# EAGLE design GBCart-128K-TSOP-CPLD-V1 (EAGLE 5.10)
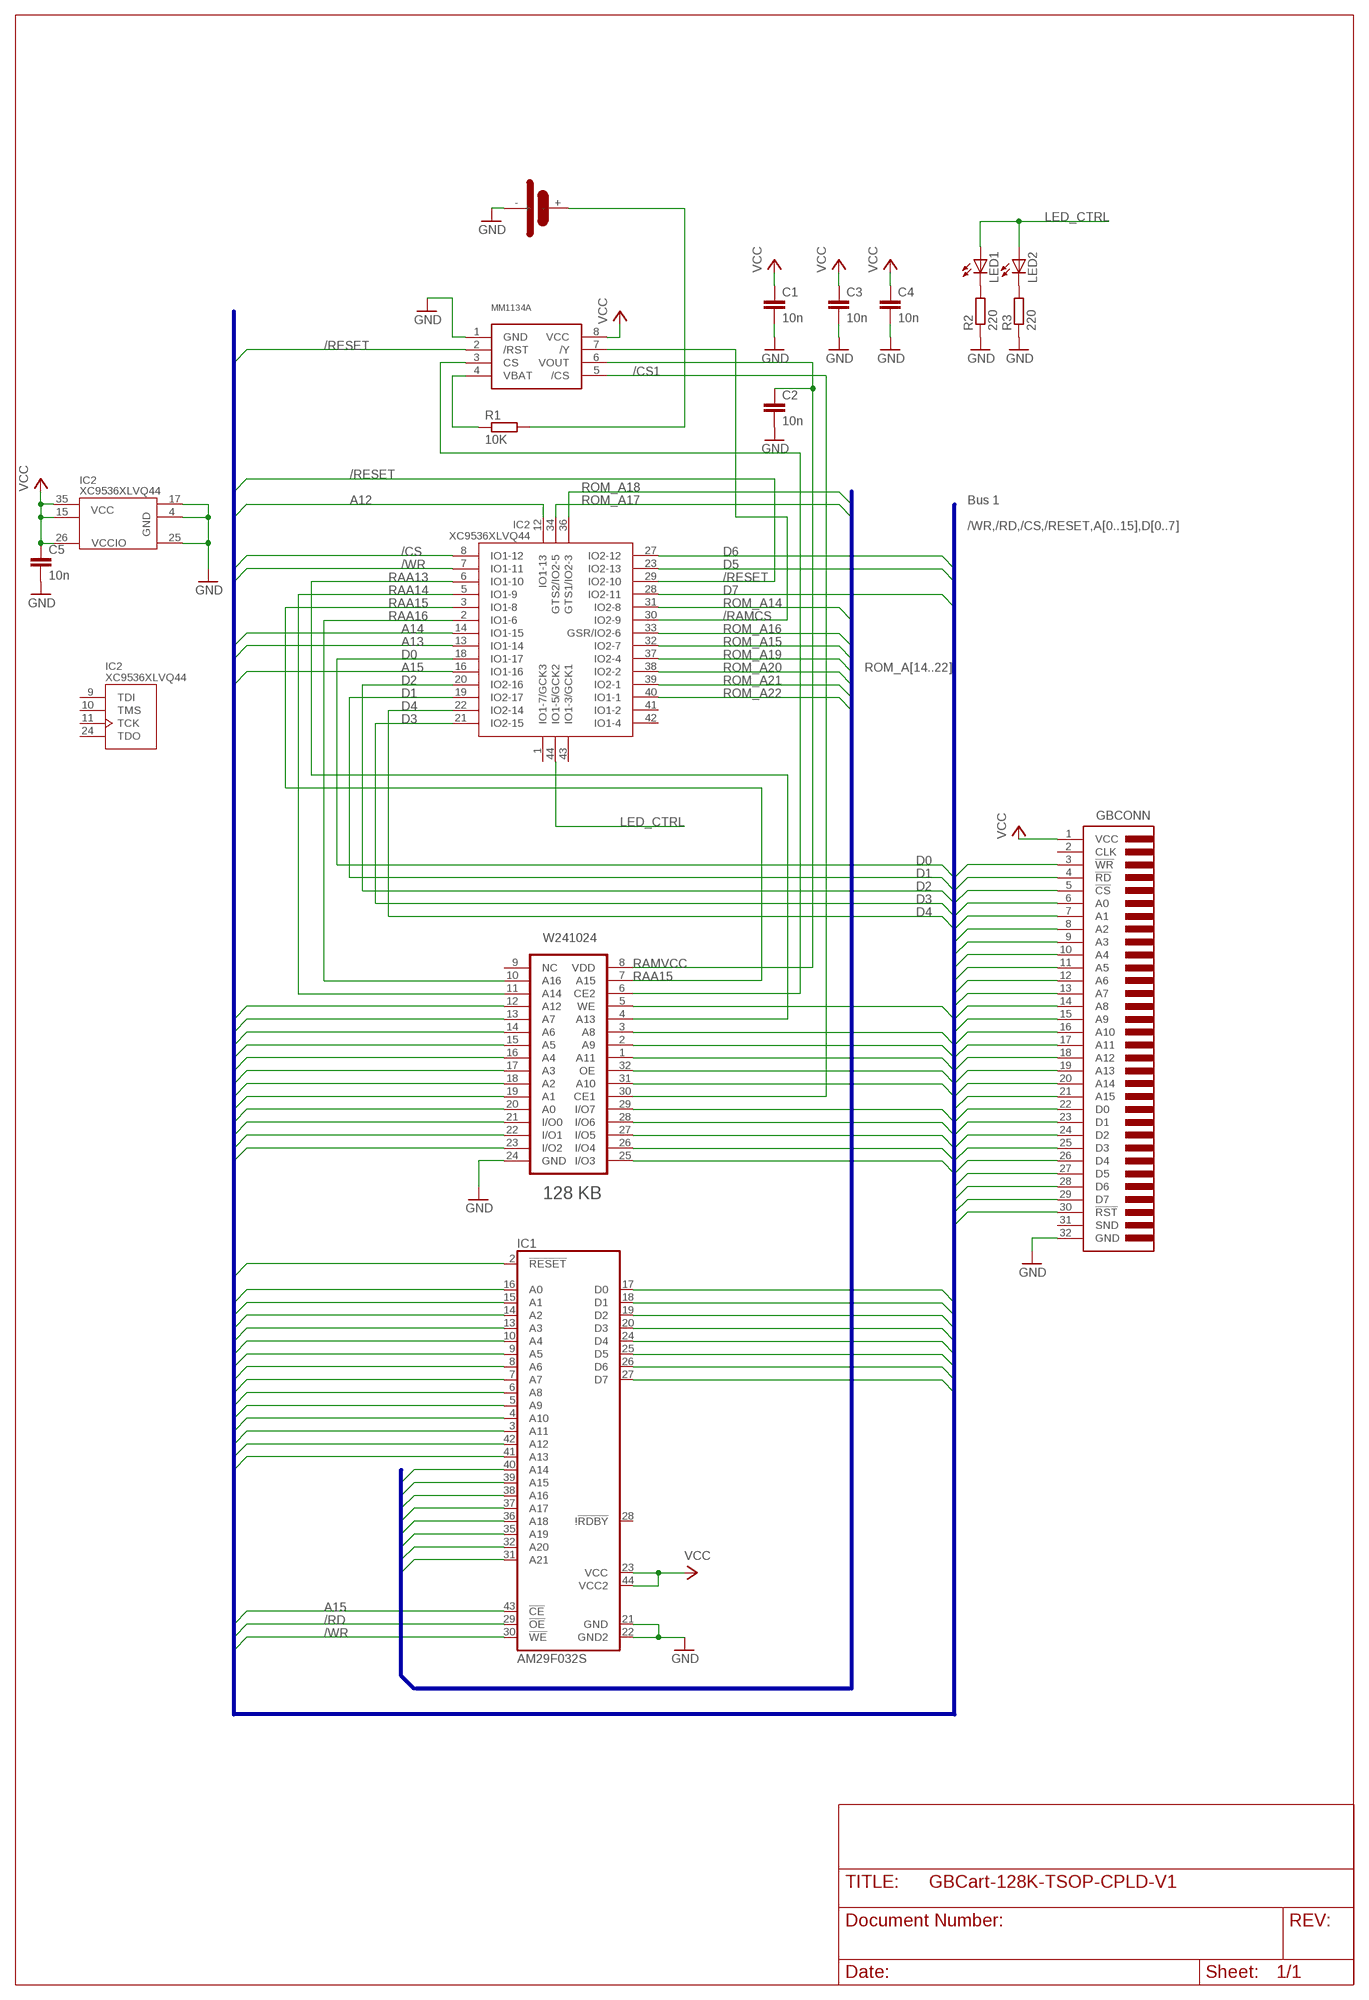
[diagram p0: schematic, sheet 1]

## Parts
C1  10n  C-EUC0805  [C0805]
C2  10n  C-EUC0805  [C0805]
C3  10n  C-EUC0805  [C0805]
C4  10n  C-EUC0805  [C0805]
C5  10n  C-EUC0805  [C0805]
GBCONN  GBCART-FULL  [GBCART]
IC1  AM29F032S  [SO44]
IC2  XC9536XLVQ44  [VQFP44]
IC3  1MBIT SRAM  W241024AT  [TSOP32]
IC4  MM1134A  [SOP08]
LED1  LEDCHIPLED_1206  [CHIPLED_1206]
LED2  LEDCHIPLED_1206  [CHIPLED_1206]
R1  10K  R-EU_R0805  [R0805]
R2  220  R-EU_R0805  [R0805]
R3  220  R-EU_R0805  [R0805]
U$1  CR1616  [CR1616]

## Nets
/CS [Signal]: GBCONN.5(!CS) IC2.8(IO1-12)
/CS1 [Signal]: IC3.30(CE1) IC4.5(/CS)
/CS2: IC3.6(CE2) IC4.3(CS)
/RAMCS [Signal]: IC2.30(IO2-9) IC4.7(/Y)
/RD [Signal]: GBCONN.4(!RD) IC1.29(!OE) IC3.32(OE)
/RESET [Signal]: GBCONN.30(!RST) IC1.2(!RESET) IC2.29(IO2-10) IC4.2(/RST)
/WR [Signal]: GBCONN.3(!WR) IC1.30(!WE) IC2.7(IO1-11) IC3.5(WE)
A0 [Signal]: GBCONN.6(A0) IC1.16(A0) IC3.20(A0)
A1 [Signal]: GBCONN.7(A1) IC1.15(A1) IC3.19(A1)
A2 [Signal]: GBCONN.8(A2) IC1.14(A2) IC3.18(A2)
A3 [Signal]: GBCONN.9(A3) IC1.13(A3) IC3.17(A3)
A4 [Signal]: GBCONN.10(A4) IC1.10(A4) IC3.16(A4)
A5 [Signal]: GBCONN.11(A5) IC1.9(A5) IC3.15(A5)
A6 [Signal]: GBCONN.12(A6) IC1.8(A6) IC3.14(A6)
A7 [Signal]: GBCONN.13(A7) IC1.7(A7) IC3.13(A7)
A8 [Signal]: GBCONN.14(A8) IC1.6(A8) IC3.3(A8)
A9 [Signal]: GBCONN.15(A9) IC1.5(A9) IC3.2(A9)
A10 [Signal]: GBCONN.16(A10) IC1.4(A10) IC3.31(A10)
A11 [Signal]: GBCONN.17(A11) IC1.3(A11) IC3.1(A11)
A12 [Signal]: GBCONN.18(A12) IC1.42(A12) IC2.12(IO1-13) IC3.12(A12)
A13 [Signal]: GBCONN.19(A13) IC1.41(A13) IC2.13(IO1-14)
A14 [Signal]: GBCONN.20(A14) IC2.14(IO1-15)
A15 [Signal]: GBCONN.21(A15) IC1.43(!CE) IC2.16(IO1-16)
D0 [Signal]: GBCONN.22(D0) IC1.17(D0) IC2.18(IO1-17) IC3.21(I/O0)
D1 [Signal]: GBCONN.23(D1) IC1.18(D1) IC2.19(IO2-17) IC3.22(I/O1)
D2 [Signal]: GBCONN.24(D2) IC1.19(D2) IC2.20(IO2-16) IC3.23(I/O2)
D3 [Signal]: GBCONN.25(D3) IC1.20(D3) IC2.21(IO2-15) IC3.25(I/O3)
D4 [Signal]: GBCONN.26(D4) IC1.24(D4) IC2.22(IO2-14) IC3.26(I/O4)
D5 [Signal]: GBCONN.27(D5) IC1.25(D5) IC2.23(IO2-13) IC3.27(I/O5)
D6 [Signal]: GBCONN.28(D6) IC1.26(D6) IC2.27(IO2-12) IC3.28(I/O6)
D7 [Signal]: GBCONN.29(D7) IC1.27(D7) IC2.28(IO2-11) IC3.29(I/O7)
GND: C1.2 C2.2 C3.2 C4.2 C5.2 GBCONN.32(GND) IC1.21(GND) IC1.22(GND2) IC2.4(GND) IC2.17(GND) IC2.25(GND) IC3.24(GND) IC4.1(GND) R2.1 R3.1 U$1.-
LED_CTRL: IC2.44(IO1-5/GCK2) LED1.A LED2.A
N$3: LED1.C R2.2
N$4: IC4.4(VBAT) R1.1
N$5: R1.2 U$1.+
N$6: LED2.C R3.2
RAA13: IC2.6(IO1-10) IC3.4(A13)
RAA14: IC2.5(IO1-9) IC3.11(A14)
RAA15: IC2.3(IO1-8) IC3.7(A15)
RAA16: IC2.2(IO1-6) IC3.10(A16)
RAMVCC: C2.1 IC3.8(VDD) IC4.6(VOUT)
ROM_A14 [Signal]: IC1.40(A14) IC2.31(IO2-8)
ROM_A15 [Signal]: IC1.39(A15) IC2.32(IO2-7)
ROM_A16 [Signal]: IC1.38(A16) IC2.33(GSR/IO2-6)
ROM_A17 [Signal]: IC1.37(A17) IC2.34(GTS2/IO2-5)
ROM_A18 [Signal]: IC1.36(A18) IC2.36(GTS1/IO2-3)
ROM_A19 [Signal]: IC1.35(A19) IC2.37(IO2-4)
ROM_A20 [Signal]: IC1.32(A20) IC2.38(IO2-2)
ROM_A21 [Signal]: IC1.31(A21) IC2.39(IO2-1)
ROM_A22: IC2.40(IO1-1)
VCC: C1.1 C3.1 C4.1 C5.1 GBCONN.1(VCC) IC1.23(VCC) IC1.44(VCC2) IC2.15(VCCINT) IC2.26(VCCIO) IC2.35(VCCINT) IC4.8(VCC)
Unconnected: GBCONN.2(CLK) GBCONN.31(SND) IC1.28(!!RDBY) IC2.1(IO1-7/GCK3) IC2.9(TDI) IC2.10(TMS) IC2.11(TCK) IC2.24(TDO) IC2.41(IO1-2) IC2.42(IO1-4) IC2.43(IO1-3/GCK1) IC3.9(NC)

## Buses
/WR,/RD,/CS,/RESET,A[0..15],D[0..7]
ROM_A[14..22]

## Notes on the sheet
- Bus 1

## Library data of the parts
C1-C5 = rcl:C-EU: CAPACITOR, European symbol
GBCONN = gameboy:GBCART
IC1 = gameboy:AM29F032S: 4-Megabit FLASH MEMORY (512 K x 8 bit/256 K x 16 Bit) 5 V-only
IC2 = enut202:XC9536XL: IC - CPLD, Xlinx 36 macrocells 34 user I/O pins
IC3 = gameboy:W241024AT
IC4 = gameboy:MM1134A
LED1 LED2 = led:LED: LED
R1-R3 = rcl:R-EU_: RESISTOR, European symbol
U$1 = gameboy:CR1616

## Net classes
0 Supply: width 0.254 mm, clearance 0.254 mm
1 Signal: width 0.15 mm, clearance 0.15 mm

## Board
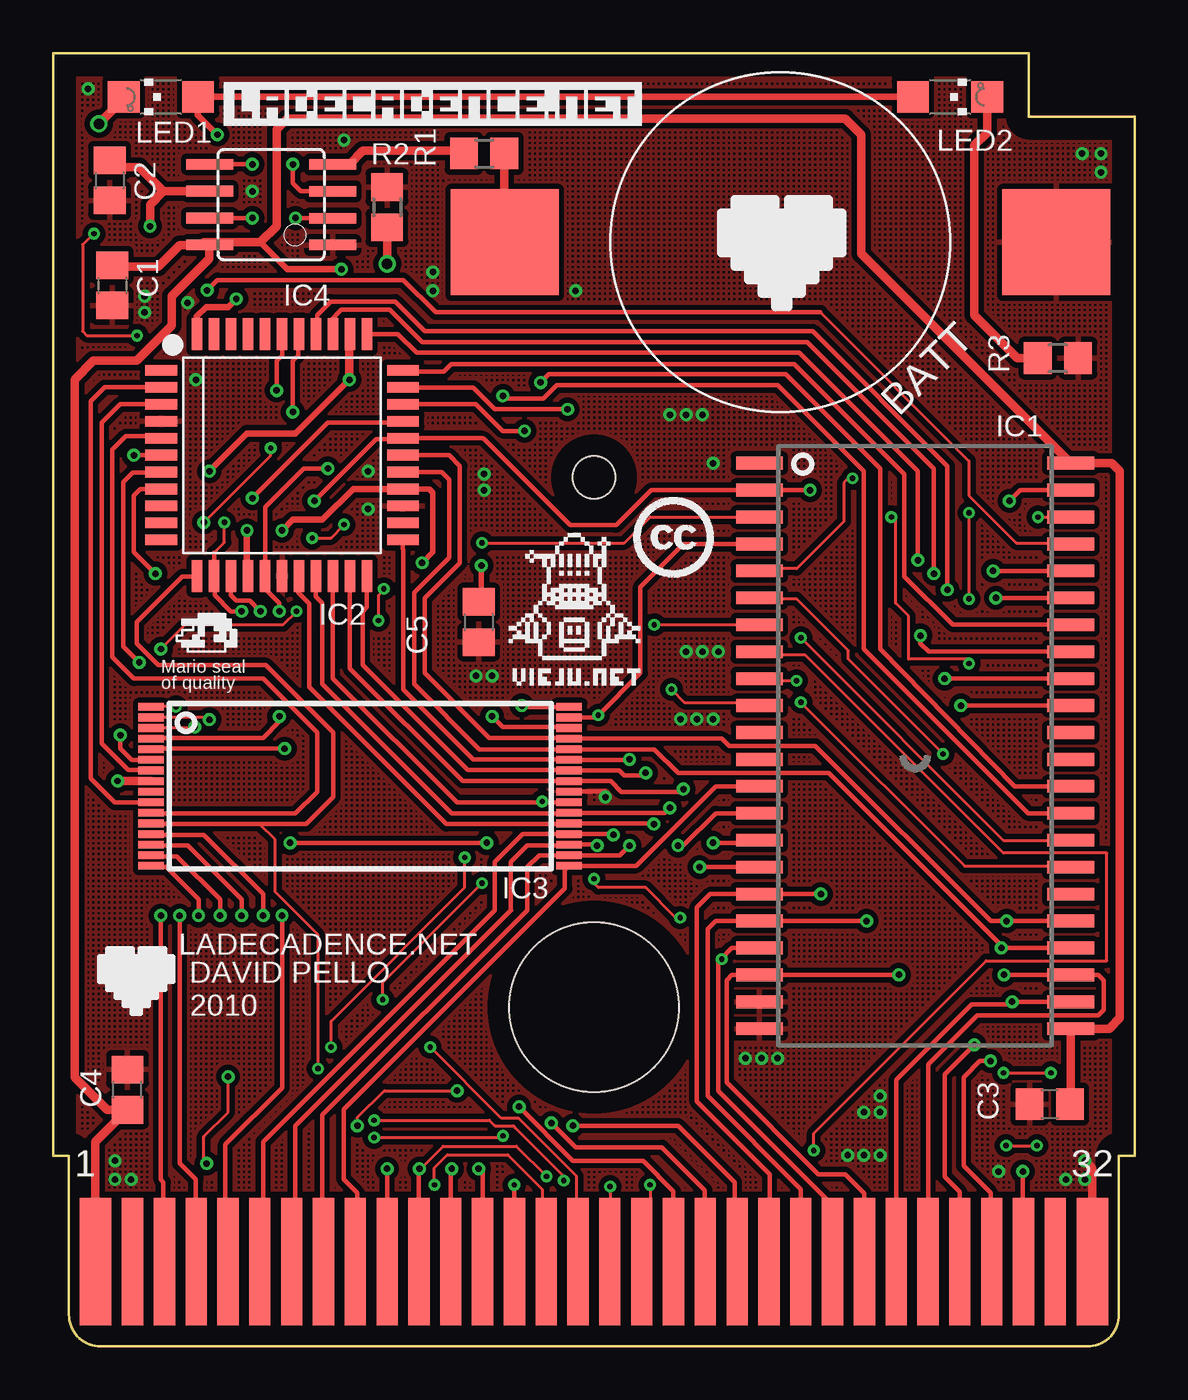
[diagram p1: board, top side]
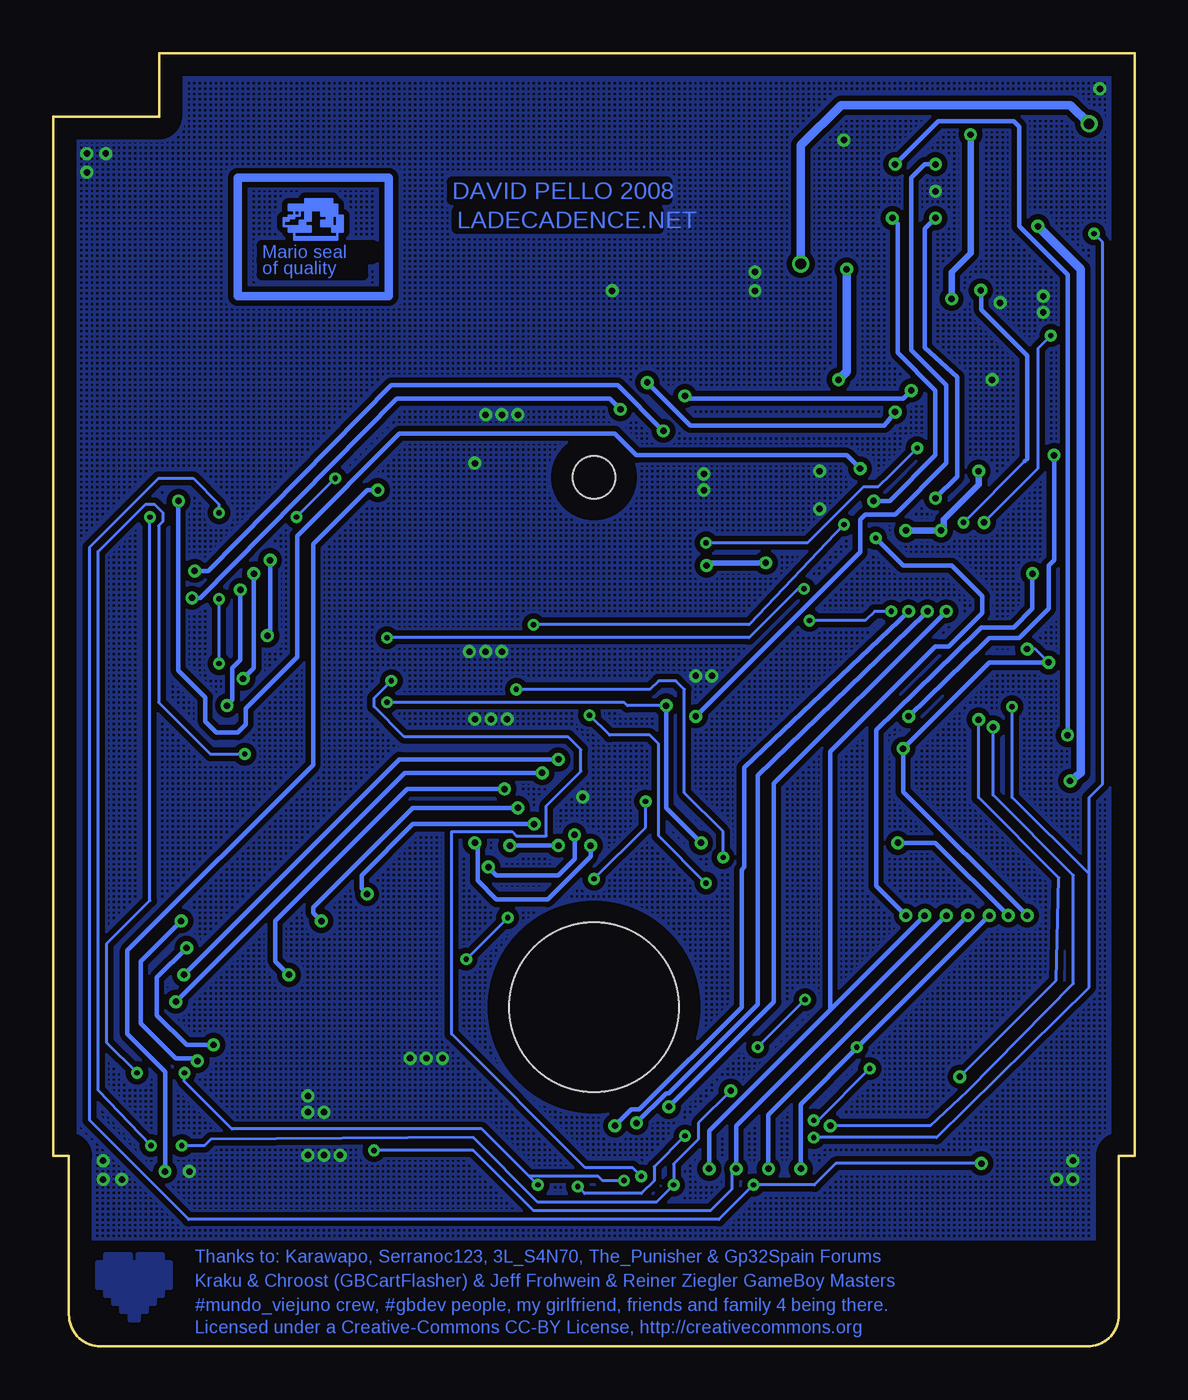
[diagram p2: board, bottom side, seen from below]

Size 51 x 61 mm. Coordinates in mm from the lower left corner, seen from the top.
Copper layers (1*16): Top 0.035mm / dielectric 1.5mm / Bottom 0.035mm
Design rules "default *": minimum track width 0.15mm, minimum drill 0.25mm, track to track 0.15mm, track to pad 0.15mm, pad to pad 0.15mm, via to via 0.15mm, smd to smd 8mil, copper to edge 40mil, drill to drill 8mil, minimum pad ring 6mil, minimum via ring 6mil, stop-mask expansion 4mil, vias tented up to drill 0mil, thermal gap 10mil

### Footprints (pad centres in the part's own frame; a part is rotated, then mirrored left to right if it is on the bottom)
C0805 = smd 1.3 x 1.5: 1 -0.95,0; 2 0.95,0
GBCART = smd 1.5 x 6: 1 -23.4,-25.21; 32 23.6,-25.21 | smd 1 x 6: 2 -21.65,-25.21; 3 -20.15,-25.21; 4 -18.65,-25.21; 5 -17.15,-25.21; 6 -15.65,-25.21; 7 -14.15,-25.21; 8 -12.65,-25.21; 9 -11.15,-25.21; 10 -9.65,-25.21; 11 -8.15,-25.21; 12 -6.65,-25.21; 13 -5.15,-25.21; 14 -3.65,-25.21; 15 -2.15,-25.21; 16 -0.65,-25.21; 17 0.85,-25.21; 18 2.35,-25.21; 19 3.85,-25.21; 20 5.35,-25.21; 21 6.85,-25.21; 22 8.35,-25.21; 23 9.85,-25.21; 24 11.35,-25.21; 25 12.85,-25.21; 26 14.35,-25.21; 27 15.85,-25.21; 28 17.35,-25.21; 29 18.85,-25.21; 30 20.35,-25.21; 31 21.85,-25.21 | hole 8: 0.1,-13.21 | hole 2: 0.1,11.79
SO44 = smd 0.6 x 2.2: 1 -13.335,-7.34; 2 -12.065,-7.34; 3 -10.795,-7.34; 4 -9.525,-7.34; 5 -8.255,-7.34; 6 -6.985,-7.34; 7 -5.715,-7.34; 8 -4.445,-7.34; 9 -3.175,-7.34; 10 -1.905,-7.34; 11 -0.635,-7.34; 12 0.635,-7.34; 13 1.905,-7.34; 14 3.175,-7.34; 15 4.445,-7.34; 16 5.715,-7.34; 17 6.985,-7.34; 18 8.255,-7.34; 19 9.525,-7.34; 20 10.795,-7.34; 21 12.065,-7.34; 22 13.335,-7.34; 23 13.335,7.34; 24 12.065,7.34; 25 10.795,7.34; 26 9.525,7.34; 27 8.255,7.34; 28 6.985,7.34; 29 5.715,7.34; 30 4.445,7.34; 31 3.175,7.34; 32 1.905,7.34; 33 0.635,7.34; 34 -0.635,7.34; 35 -1.905,7.34; 36 -3.175,7.34; 37 -4.445,7.34; 38 -5.715,7.34; 39 -6.985,7.34; 40 -8.255,7.34; 41 -9.525,7.34; 42 -10.795,7.34; 43 -12.065,7.34; 44 -13.335,7.34
VQFP44 = smd 0.5 x 1.5: 1 -4,-5.7; 2 -3.2,-5.7; 3 -2.4,-5.7; 4 -1.6,-5.7; 5 -0.8,-5.7; 6 0,-5.7; 7 0.8,-5.7; 8 1.6,-5.7; 9 2.4,-5.7; 10 3.2,-5.7; 11 4,-5.7; 23 4,5.7; 24 3.2,5.7; 25 2.4,5.7; 26 1.6,5.7; 27 0.8,5.7; 28 0,5.7; 29 -0.8,5.7; 30 -1.6,5.7; 31 -2.4,5.7; 32 -3.2,5.7; 33 -4,5.7 | smd 1.5 x 0.5: 12 5.7,-4; 13 5.7,-3.2; 14 5.7,-2.4; 15 5.7,-1.6; 16 5.7,-0.8; 17 5.7,0; 18 5.7,0.8; 19 5.7,1.6; 20 5.7,2.4; 21 5.7,3.2; 22 5.7,4; 34 -5.7,4; 35 -5.7,3.2; 36 -5.7,2.4; 37 -5.7,1.6; 38 -5.7,0.8; 39 -5.7,0; 40 -5.7,-0.8; 41 -5.7,-1.6; 42 -5.7,-2.4; 43 -5.7,-3.2; 44 -5.7,-4
TSOP32 = smd 1.2 x 0.36: 1 -9.85,3.75; 2 -9.85,3.25; 3 -9.85,2.75; 4 -9.85,2.25; 5 -9.85,1.75; 6 -9.85,1.25; 7 -9.85,0.75; 8 -9.85,0.25; 9 -9.85,-0.25; 10 -9.85,-0.75; 11 -9.85,-1.25; 12 -9.85,-1.75; 13 -9.85,-2.25; 14 -9.85,-2.75; 15 -9.85,-3.25; 16 -9.85,-3.75; 17 9.85,-3.75; 18 9.85,-3.25; 19 9.85,-2.75; 20 9.85,-2.25; 21 9.85,-1.75; 22 9.85,-1.25; 23 9.85,-0.75; 24 9.85,-0.25; 25 9.85,0.25; 26 9.85,0.75; 27 9.85,1.25; 28 9.85,1.75; 29 9.85,2.25; 30 9.85,2.75; 31 9.85,3.25; 32 9.85,3.75
SOP08 = smd 0.5 x 2.2: 1 -1.905,-2.9; 2 -0.645,-2.9; 3 0.625,-2.9; 4 1.895,-2.9; 5 1.905,2.9; 6 0.635,2.9; 7 -0.635,2.9; 8 -1.905,2.9
CHIPLED_1206 = smd 1.5 x 1.5: A 0,-1.75; C 0,1.75
R0805 = smd 1.3 x 1.5: 1 -0.95,0; 2 0.95,0
CR1616 = smd 5.08 x 5: + -13,0; - 13,0

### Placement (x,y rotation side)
C1  2.79,50.04 270 top
C2  2.67,54.99 270 top
C3  46.99,11.43 180 top
C4  3.51,12.11 90 top
C5  20.07,34.16 270 top
GBCONN  25.4,29.21 0 top
IC1  40.64,28.32 270 top
IC2  10.79,42.04 270 top
IC3  14.48,26.42 0 top
IC4  10.29,53.85 90 top
LED1  5.08,58.93 90 top
LED2  42.29,58.93 270 top
R1  20.32,56.26 0 top
R2  15.75,53.72 270 top
R3  47.37,46.61 180 top
U$1  34.29,52.07 0 top
U$2  [MARIOSEAL]  38.61,52.58 0 top
U$3  [CC]  27.37,36.27 0 top
U$4  [VIEJU]  20.77,31.07 0 top
U$5  [CORAZON-SILK]  3.86,17.48 0 top
U$6  [LADECADENCE-TEXT-INV]  8.13,57.66 0 top
U$7  [MARIOSEAL-SILK]  4.7,30.48 0 top

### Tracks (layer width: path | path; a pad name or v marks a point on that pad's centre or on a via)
/CS  (via drill 0.3 pad 0.61)
  Top 0.203: GBCONN.5 8.13,4.12 8.13,9.53 10.79,12.19 v10.79,20.32 | v4.83,36.45 3.81,37.47 3.81,40.13 4.12,40.44 IC2.8
  Bottom 0.203: v4.83,36.45 4.83,34.8 5.71,33.91 7.24,33.91 7.49,33.66 12.19,29.08 12.19,21.72 v10.79,20.32
/CS1  (via drill 0.3 pad 0.61)
  Top 0.203: v9.4,55.75 IC4.5 | v20.7,29.72 21.21,29.21 24.28,29.21 IC3.30
  Bottom 0.203: v9.4,55.75 9.91,55.75 10.54,55.12 10.54,46.99 8.89,45.34 8.89,41.66 11.3,39.24 12.7,39.24 12.95,38.99 12.95,37.47 v20.7,29.72
/CS2  (via drill 0.3 pad 0.61)
  Top 0.203: IC4.3 13.18,54.48 11.68,54.48 11.3,54.86 v11.3,55.75 | v3.17,28.83 3.17,28.19 3.7,27.67 IC3.6
  Bottom 0.203: v11.3,55.75 9.27,57.79 5.71,57.79 5.46,57.53 5.46,52.83 3.17,50.55 v3.17,28.83
/RAMCS  (via drill 0.3 pad 0.61)
  Top 0.203: v9.4,53.21 IC4.7 | v9.4,40.01 12.95,43.56 16.42,43.56 IC2.30
  Bottom 0.203: v9.4,53.21 9.91,52.71 9.91,47.12 8.38,45.72 8.38,41.02 v9.4,40.01
/RD  (via drill 0.25, 0.3 pad 0.61)
  Top 0.15: v35.26,30.38 42.98,22.66 47.85,22.66 IC1.29
  Top 0.203: GBCONN.4 6.73,6.43 6.73,7.87 5.97,8.64 v5.97,20.32 | v11.18,23.75 v20.45,23.75 | v22.1,30.23 22.16,30.17 IC3.32
  Bottom 0.15: 24.08,30.38 v35.26,30.38
  Bottom 0.152: 24.08,30.38 23.93,30.23 v22.1,30.23
  Bottom 0.203: v5.97,20.32 9.4,23.75 v11.18,23.75 | v20.45,23.75 22.1,25.4 v22.1,30.23
/RESET  (via drill 0.3 pad 0.61)
  Top 0.203: IC4.2 13.18,53.21 v11.43,53.21 | GBCONN.30 45.72,4.03 v45.72,8.26 | v35.69,40.39 IC1.2 28.19,40.39 26.54,38.73 24.38,38.73 20.32,42.8 20.23,42.84 IC2.29 16.46,42.8 15.24,42.8 v12.32,39.88
  Bottom 0.203: v11.43,53.21 11.18,52.96 11.18,46.86 9.4,45.09 9.4,42.04 11.56,39.88 v12.32,39.88 | v45.72,8.26 45.72,12.95 47.5,14.73 47.5,18.67 38.73,27.43 38.73,37.85 36.2,40.39 v35.69,40.39
/WR  (via drill 0.25, 0.3 pad 0.61)
  Top 0.15: v35.26,33.43 44.81,23.88 IC1.30 | v15.34,34.24 15.37,34.24 15.37,35.43 15.62,35.69 v15.6,35.74 | v11.48,34.67 10.85,34.04 9.02,34.04
  Top 0.152: 9.02,34.04 6.22,34.04 v5.08,32.89
  Top 0.203: v4.06,32.26 3.3,33.02 3.3,40.77 3.75,41.22 5.08,41.22 IC2.7 | v10.92,28.19 4.66,28.19 IC3.5 | GBCONN.3 5.21,4.04 5.21,7.75 5.08,7.87 v5.08,20.32 | v11.48,34.67 11.47,34.66
  Bottom 0.15: v35.26,33.43 18.19,33.43 15.75,35.87 v15.6,35.74 | v15.34,34.24 12.7,34.24 12.27,34.67 v11.48,34.67
  Bottom 0.152: v5.08,32.89 4.7,32.89 v4.06,32.26
  Bottom 0.203: v4.06,32.26 6.86,32.26 v10.92,28.19 10.92,26.16 v5.08,20.32
A0  (via drill 0.3 pad 0.61)
  Top 0.203: GBCONN.6 9.91,4.16 9.91,9.65 20.83,20.57 20.83,22.86 22.13,24.17 IC3.20 26.38,24.17 v26.42,24.13 | v30.48,22.61 IC1.16
  Bottom 0.203: v26.42,24.13 26.42,22.99 27.18,22.23 30.1,22.23 v30.48,22.61
A1  (via drill 0.3 pad 0.61)
  Top 0.203: GBCONN.7 11.37,4 11.43,4.06 11.43,10.41 21.59,20.57 21.59,22.86 22.35,23.62 24.28,23.62 IC3.19 25.61,23.67 v25.65,23.62 | v31.11,23.75 33.17,23.75 IC1.15
  Bottom 0.203: v25.65,23.62 25.65,23.11 27.69,21.08 30.1,21.08 30.99,21.97 30.99,23.62 v31.11,23.75
A2  (via drill 0.3 pad 0.61)
  Top 0.203: GBCONN.8 12.95,4.2 12.95,5.33 12.7,5.59 12.7,10.92 22.35,20.57 22.35,22.61 22.91,23.17 IC3.18 26.72,23.17 v27.18,23.62 | v29.46,23.62 29.72,23.62 31.24,25.15 IC1.14
  Bottom 0.203: v27.18,23.62 v29.46,23.62
A3
  Top 0.203: GBCONN.9 14.41,4 14.48,4.06 14.48,4.45 14.35,4.57 14.35,7.24 13.72,7.87 13.72,11.18 24.13,21.59 24.13,22.47 IC3.17 27.49,22.67 31.24,26.42 IC1.13
A4  (via drill 0.25, 0.3 pad 0.61)
  Top 0.15: v29.16,30.99 29.77,30.38 33.22,30.38 IC1.10 | v19.41,23.06 19.41,21.64 13.11,15.34 v13.11,14.12
  Top 0.203: GBCONN.10 v15.75,8.38 | v6.86,20.32 6.86,21.08 5.33,22.61 4.69,22.61 IC3.16
  Bottom 0.15: v29.16,30.99 22.86,30.99 22.45,31.39 21.64,31.39 21.23,30.99 21.23,26.11 19.41,24.28 v19.41,23.06 | 13.08,14.1 v13.11,14.12
  Bottom 0.203: v15.75,8.38 15.75,11.43 13.08,14.1 v6.86,20.32
A5  (via drill 0.25, 0.3 pad 0.61)
  Top 0.15: v35.05,31.39 33.43,31.39 IC1.9 | v23.27,8.03 21.84,9.45 18.39,9.45 17.37,8.43 v17.27,8.38
  Top 0.203: GBCONN.11 17.25,8.36 v17.27,8.38 | v7.87,20.32 7.87,21.08 5.84,23.11 4.68,23.11 IC3.15
  Bottom 0.15: v35.05,31.39 35.87,30.58 35.87,30.18 34.44,28.75 26.72,28.75 26.11,28.14 26.11,27.13 27.74,25.5 27.74,24.08 29.16,24.08 29.36,24.28 32.21,24.28 32.21,14.73 25.91,8.43 23.67,8.43 v23.27,8.03
  Bottom 0.203: v17.27,8.38 17.27,10.92 v7.87,20.32
A6  (via drill 0.25, 0.3 pad 0.61)
  Top 0.15: v35.87,9.25 35.87,10.06 43.99,18.19 49.68,18.19 49.68,23.27 44.81,23.27 35.46,32.61 33.43,32.61 IC1.8
  Top 0.203: GBCONN.12 18.75,8.08 v18.8,8.38 | v8.89,20.32 8.89,21.08 6.35,23.62 4.67,23.62 IC3.14
  Bottom 0.15: v35.87,9.25 31.19,9.25 28.35,6.4 20.02,6.4 19,7.42 19,8.43 18.8,8.64
  Bottom 0.203: v18.8,8.38 18.8,8.64 18.8,10.41 v8.89,20.32
A7  (via drill 0.25, 0.3 pad 0.61)
  Top 0.15: v12.22,38.12 13.11,38.12 13.72,38.73 v13.72,38.76 | v28.35,34.04 IC1.7
  Top 0.203: GBCONN.13 20.25,8.2 v20.07,8.38 | v9.91,20.32 9.91,21.34 7.11,24.13 4.66,24.13 IC3.13
  Bottom 0.15: v28.35,34.04 18.19,34.04 v13.72,38.76 | 12.88,17.35 12.9,17.37
  Bottom 0.203: v20.07,8.38 20.07,10.16 14.35,15.88 | v9.91,20.32 12.88,17.35 14.35,15.88 | 14.35,15.88 14.35,28.07 9.4,33.02 8.76,33.02 7.19,34.59 7.19,35.38 8.64,36.83 10.92,36.83 v12.22,38.12
A8  (via drill 0.25, 0.3 pad 0.61)
  Top 0.15: v41.96,27.94 37.49,32.41 37.49,32.82 35.05,35.26 33.43,35.26 IC1.6 | v44.93,9.47 v46.38,9.47 | v21.74,7.62 v21.75,7.62
  Top 0.152: IC3.3 6.64,29.17 v6.68,29.21 | v19.05,12.07 15.62,12.07 14.35,10.8 v14.35,10.41
  Top 0.203: v21.75,7.62 GBCONN.14
  Bottom 0.15: v41.96,27.94 43.59,27.94 46.02,30.38 46.02,38.71 45.82,38.91 | 46.23,39.73 46.63,39.73 48.87,37.49 48.87,12.09 v46.38,9.47 | v44.93,9.47 43.87,9.47 43.56,9.78 31.19,9.86 28.14,6.81 22.55,6.81 v21.74,7.62
  Bottom 0.152: v6.68,29.21 6.68,26.01 2.9,22.23 2.9,17.12 7.87,12.07 9.65,10.41 v14.35,10.41 | v21.74,7.62 21.74,8.61 20.57,9.78 20.57,10.54 v19.05,12.07 | 46.23,39.73 45.82,39.32 45.82,38.91
A9  (via drill 0.25, 0.3 pad 0.61)
  Top 0.15: v37.69,40.95 37.49,40.95 37.29,40.74 37.29,38.91 35.05,36.68 33.43,36.68 IC1.5 | v39.52,39.12 39.73,39.12 39.73,35.05 40.34,34.44 40.34,32.41 43.18,32.41 v43.18,32.21 | v43.18,39.32 v43.18,35.26 | v17.98,7.62 17.98,8.43 18.59,9.04 21.44,9.04 23.06,7.42 23.06,4.17 GBCONN.15
  Top 0.152: IC3.2 7.27,29.67 v7.37,29.57 | v8.26,12.73 8.26,11.05 7.11,9.91 7.11,8.76 v7.24,8.64
  Top 0.203: IC3.2 4.6,29.64
  Bottom 0.15: v43.18,35.26 v43.18,32.21 | v43.18,39.32 43.18,39.73 44.4,40.95 46.02,40.95 49.28,37.69 49.28,10.67 44.6,5.99 19.61,5.99 v17.98,7.62
  Bottom 0.152: v7.37,29.57 7.37,25.88 3.58,22.1 3.71,17.27 v8.26,12.73 | v7.24,8.64 14.1,8.64 15.11,7.62 v17.98,7.62 | v39.52,39.12 v37.69,40.95
A10  (via drill 0.25)
  Top 0.15: v17.78,14.12 21.13,10.77 21.95,10.77 24.69,8.03 24.69,4.17 GBCONN.16 | v15.54,16.36 15.54,17.17 v20.22,21.84
  Top 0.203: IC3.31 25.6,29.67 v25.7,29.77 27.69,31.75 27.69,35.81 29.72,37.85 IC1.4
  Bottom 0.15: v17.78,14.12 v15.54,16.36 | v20.22,21.84 22.45,24.08 22.45,28.42 22.86,28.83
  Bottom 0.152: 22.86,28.83 24.77,28.83 v25.7,29.77
A11  (via drill 0.25, 0.3 pad 0.61)
  Top 0.15: v5.79,30.18 4.78,30.18 IC3.1 | v15.14,9.86 21.13,9.86 v21.21,9.93 | v26.26,7.54 26.26,4.9 26.11,4.17 GBCONN.17 | v20.22,37.9 26.92,37.9 28.14,39.12 IC1.3 | v3.96,47.68 1.6,47.68 1.4,47.88 1.4,51.97 v1.93,52.48
  Top 0.152: v7.11,38.86 10.26,42.01 v10.26,42.37
  Bottom 0.15: v5.79,30.18 5.79,25.88 2.16,22.28 2.16,16.94 9.35,9.86 v15.14,9.86 | v21.21,9.93 22.66,8.48 22.66,7.82 23.27,7.21 25.93,7.21 v26.26,7.54 | v20.22,37.9 15.44,37.9 12.8,40.54 12.12,40.54 11.48,41.15 v10.26,42.37 | v1.93,52.48 1.52,52.07 1.52,26.52 2.16,25.88
  Bottom 0.152: v3.96,47.68 4.57,47.07 4.57,41.4 v7.11,38.86 | 2.16,22.28 2.16,25.88
A12  (via drill 0.25)
  Top 0.15: v44.81,12.9 v47.04,12.9 | v28.14,7.62 28.14,4.37 27.94,4.17 GBCONN.18 | v46.43,39.12 IC1.42 | 10.46,21.44 12.5,19.41 v12.5,13.11 | v15.14,10.67 20.57,10.67 20.83,10.41 21.72,10.41 21.82,10.29 24.08,8.03 v24.08,7.82
  Top 0.152: 10.46,21.44 10.46,23.9 9.73,24.64
  Top 0.203: IC3.12 4.66,24.64 9.73,24.64 11.94,24.64 13.21,25.91 13.21,28.96 10.03,32.13 4.95,32.13 3.94,33.15 3.94,34.16 6.1,36.32 6.78,36.32 IC2.12 6.73,36.27
  Bottom 0.15: v46.43,39.12 46.43,21.03 48.46,19 48.46,14.33 v47.04,12.9 | v44.81,12.9 44.81,12.5 42.57,10.26 30.79,10.26 28.55,8.03 | 28.55,8.03 v28.14,7.62 | v12.5,13.11 14.94,10.67 v15.14,10.67 | v24.08,7.82 25.09,7.82 25.3,8.03 28.55,8.03
A13  (via drill 0.25, 0.3 pad 0.61)
  Top 0.15: 36.17,48.77 43.18,41.76 43.18,40.13 45.41,37.9 47.85,37.9 IC1.41
  Top 0.152: 7.59,37.44 8.08,37.92 v8.08,38.86
  Top 0.203: GBCONN.19 29.25,7.33 27.81,8.76 24.51,8.76 v21.97,11.3 | v8.89,34.67 8.38,34.67 7.62,35.43 7.62,36.31 IC2.13 7.59,37.44 | 36.17,48.77 18.03,48.77 16.51,50.29 7.75,50.29 v7.26,49.81
  Bottom 0.15: v8.08,38.86 5.18,41.76
  Bottom 0.203: v8.89,34.67 17.02,26.54 17.02,16.26 v21.97,11.3 | 5.18,41.76 5.08,41.86 5.08,46.74 7.24,48.9 7.24,49.66 v7.26,49.81
A14  (via drill 0.3 pad 0.61)
  Top 0.203: GBCONN.20 30.73,4.02 30.73,7.37 28.7,9.4 24.64,9.4 v23.5,10.54 | v9.78,34.67 9.27,35.18 8.64,35.18 8.38,35.43 8.38,36.32 IC2.14
  Bottom 0.203: v9.78,34.67 9.91,34.54 17.78,26.92 17.78,16.13 21.97,11.94 22.1,11.94 v23.5,10.54
A15  (via drill 0.3 pad 0.25, 0.3 pad 0.61)
  Top 0.203: GBCONN.21 32.13,4.12 32.13,7.75 29.46,10.41 v24.51,10.41 | v12.95,41.4 11.81,41.4 9.99,39.59 IC2.16 10.03,36.3 10.03,35.69 10.67,35.05 v10.67,34.67 | v45.09,39.88 45.59,40.39 IC1.43
  Bottom 0.203: v10.67,34.67 18.41,27.31 18.41,22.61 18.54,22.48 18.54,16 23.37,11.18 23.75,11.18 v24.51,10.41 | v12.95,41.4 13.59,42.04 23.5,42.04 24.51,43.05 34.67,43.05 39.5,38.23 39.5,32.51 41.91,30.1 41.91,29.34 42.29,28.96 43.31,28.96 43.81,29.46 43.81,30.61 45.09,31.88 v45.09,39.88
D0  (via drill 0.3 pad 0.61)
  Top 0.203: GBCONN.22 33.78,4 33.78,8.13 30.35,11.56 30.35,20.7 30.99,21.34 IC1.17 v36.2,21.34 | v28.32,24.64 28.29,24.67 IC3.21 24.3,24.64 18.54,24.64 12.08,31.1 12.08,35.03 11.56,35.56 11.56,36.3 IC2.18
  Bottom 0.203: v28.32,24.64 34.04,24.64 36.45,22.23 36.45,21.59 v36.2,21.34
D1  (via drill 0.3 pad 0.61)
  Top 0.203: GBCONN.23 35.25,7.42 30.86,11.81 30.86,19.69 31.24,20.07 IC1.18 v38.35,20.07 | v29.08,25.4 28.85,25.17 IC3.22 24.31,25.15 18.8,25.15 12.7,31.24 12.7,35.05 12.39,35.36 IC2.19
  Bottom 0.203: v29.08,25.4 34.04,25.4 38.73,20.7 38.73,20.45 v38.35,20.07
D2  (via drill 0.25)
  Top 0.15: v25.5,22.05 25.5,21.84 25.7,21.64 27.94,21.64 29.36,20.22 v29.57,20.22 | v23.06,25.71 23.06,25.65
  Top 0.203: GBCONN.24 37,6.43 31.37,12.07 31.37,18.11 v31.52,18.26 31.5,18.29 32,18.8 IC1.19 | IC3.23 24.32,25.65 23.06,25.65 19.05,25.65 13.2,31.51 IC2.20
  Bottom 0.15: v23.06,25.71 23.06,24.49 v25.5,22.05 | v31.52,18.26 v29.57,20.22
D3  (via drill 0.3 pad 0.61)
  Top 0.203: GBCONN.25 38.25,7.22 37.34,8.13 36.07,8.13 31.75,12.45 31.75,17.27 32,17.53 IC1.20 v39.88,17.53 | v29.72,26.29 29.59,26.16 26.8,26.16 26.29,26.67 IC3.25 19.3,26.67 13.99,31.98 IC2.21
  Bottom 0.203: v29.72,26.29 34.29,26.29 40.51,20.07 40.51,18.16 v39.88,17.53
D4  (via drill 0.3 pad 0.61)
  Top 0.203: v27.94,27.05 27.81,26.92 26.92,26.92 26.68,27.17 IC3.26 24.32,27.18 19.56,27.18 14.61,32.13 14.61,34.67 14.79,34.86 IC2.22 | IC1.24 v45.21,16.26 45.09,16.13 43.31,16.13 39.75,12.57 GBCONN.26
  Bottom 0.203: v27.94,27.05 34.42,27.05 v45.21,16.26
D5  (via drill 0.3 pad 0.61)
  Top 0.203: v27.18,27.69 27.16,27.67 IC3.27 24.31,27.69 19.81,27.69 16.51,30.99 16.51,37.59 16.5,37.61 IC2.23 | v44.83,17.53 IC1.25 49.28,17.53 49.53,17.27 49.53,15.88 49.28,15.62 43.56,15.62 41.25,13.31 GBCONN.27
  Bottom 0.203: v27.18,27.69 34.67,27.69 v44.83,17.53
D6  (via drill 0.3 pad 0.61)
  Top 0.203: 44.83,18.8 36.58,27.05 29.46,27.05 28.35,28.17 IC3.28 20.09,28.17 17.02,31.24 17.02,35.56 18.67,37.21 18.67,40.89 18.33,41.24 IC2.27 | GBCONN.28 42.75,7.29 42.04,8 42.04,12.83 v43.43,14.22 | v44.7,18.8 44.83,18.8 | 44.83,18.8 IC1.26
  Bottom 0.203: v43.43,14.22 44.7,14.22 46.1,15.62 46.1,17.4 v44.7,18.8
D7  (via drill 0.3 pad 0.61)
  Top 0.203: GBCONN.29 44.45,4 44.45,5.59 44.2,5.84 44.2,7.24 42.93,8.51 42.93,12.7 43.69,13.46 v44.2,13.46 | IC1.27 v44.96,20.07 44.2,20.07 35.94,28.32 31.88,28.32 31.53,28.67 IC3.29 24.29,28.7 20.57,28.7 17.53,31.75 17.53,35.31 19.18,36.96 19.18,41.53 18.67,42.04 IC2.28
  Bottom 0.203: v44.2,13.46 44.32,13.59 45.21,13.59 46.86,15.24 46.86,18.16 v44.96,20.07
GND  (via drill 0.3 pad 0.61)
  Top 0.203: v26.04,25.91 26.03,26.17 IC3.24
  Top 0.406: GBCONN.32 49,8.4 v48.64,8.76
  other vias: 47.75,7.87 48.64,7.87 1.65,59.31 1.65,59.31 1.65,59.31 2.92,8.76 2.92,7.87 3.68,7.87 49.4,55.37 48.51,56.26 49.4,56.26 17.91,49.78 17.91,50.67 24.64,49.78 29.08,43.94 30.61,43.94 29.84,43.94 20.32,41.15 31.11,41.66 20.32,40.39 14.86,41.28 4.32,48.77 4.32,49.53 6.35,49.23 6.73,45.59 32.64,13.59 33.4,13.59 34.16,13.59 38.99,11.81 38.23,11.05 38.99,11.05 37.47,9.02 38.23,9.02 38.99,9.02 44.58,8.26 20.7,31.62 19.94,31.62 31.37,32.77 30.61,32.77 29.84,32.77 31.11,29.59 30.35,29.59 29.59,29.59 14.86,39.5 9.4,54.48 13.72,56.9
  pour Top (hatched): 0.38,60.58 45.97,60.96 45.97,57.91 50.67,57.91 50.67,7.37 0.25,7.37 0.25,7.62 0.38,7.62
  pour Bottom (hatched): 0.25,60.83 45.85,61.09 45.85,60.96 46.1,60.96 46.1,58.04 50.93,58.04 50.93,4.95 50.8,5.08 0,5.08 0.25,5.33
LED_CTRL  (via drill 0.3)
  Top 0.305: LED2.A LED1.A 6.83,58.07 v7.75,57.15 | v8.64,49.4 8.26,49.02 7.21,49.02 6.78,48.59 6.78,47.75
  Top 0.406: 6.81,47.75 IC2.44 6.78,47.75
  Bottom 0.305: v7.75,57.15 7.75,51.56 8.64,50.67 v8.64,49.4
N$3  (via drill 0.5 pad 0.3)
  Top 0.406: LED1.C 3.43,58.93 v2.16,57.66 | v15.75,51.05 R2.2
  Bottom 0.406: v2.16,57.66 3.05,58.55 13.84,58.55 15.75,56.64 v15.75,51.05
N$4
  Top 0.406: R1.1 18.91,56.39 14.61,56.39 13.96,55.74 IC4.4
N$5
  Top 0.406: R1.2 21.27,52.09 U$1.+
N$6
  Top 0.406: LED2.C 44.04,57.25 43.43,56.64 43.43,48.64 45.47,46.61 R3.2
N$10
  pour Bottom: 46.99,3.94 47.37,3.94 47.37,4.32 48.51,4.32 48.51,3.94 48.9,3.94 48.9,2.79 48.51,2.79 48.51,2.41 48.13,2.41 48.13,2.03 47.75,2.03 47.75,1.65 47.37,1.65 47.37,1.27 46.99,1.27 46.99,1.65 46.61,1.65 46.61,2.03 46.23,2.03 46.23,2.41 45.85,2.41 45.85,2.79 45.47,2.79 45.47,3.94 45.85,3.94 45.85,4.32 46.99,4.32
N$11
  Bottom 0.406: 42.29,49.53 42.29,55.12 35.18,55.12 35.18,49.53 42.29,49.53
RAA13  (via drill 0.3 pad 0.61)
  Top 0.203: v10.67,29.72 10.67,29.46 9.91,28.7 4.66,28.7 IC3.4 | v3.81,42.04 IC2.6
  Bottom 0.203: v10.67,29.72 7.11,33.15 6.86,33.4 5.46,33.4 4.06,34.8 4.06,36.83 3.81,37.08 v3.81,42.04
RAA14
  Top 0.203: IC3.11 4.65,25.15 11.43,25.15 12.45,26.16 12.45,28.96 9.91,31.5 3.81,31.5 2.79,32.51 2.79,42.29 3.43,42.93 5.01,42.93 IC2.5
RAA15
  Top 0.203: IC3.7 4.62,27.18 3.56,27.18 2.29,28.45 2.29,43.56 3.16,44.44 IC2.3
RAA16
  Top 0.203: IC3.10 4.62,25.65 2.92,25.65 1.78,26.8 1.78,44.58 2.44,45.24 IC2.2
RAMVCC  (via drill 0.3 pad 0.61)
  Top 0.406: 5.21,54.48 IC4.6 | 5.21,54.48 4.06,55.63 2.73,55.63 C2.1 | 5.21,54.48 4.57,53.85 v4.57,52.83 | v3.05,26.67 3.42,26.67 IC3.8
  Bottom 0.406: v4.57,52.83 2.54,50.8 2.54,27.05 v3.05,26.67
ROM_A14  (via drill 0.3 pad 0.61)
  Top 0.203: v44.32,36.58 IC1.40 | v22.23,43.18 21.21,43.18 19.94,44.45 16.51,44.45 IC2.31
  Bottom 0.203: v44.32,36.58 43.69,36.58 35.05,45.34 24.38,45.34 v22.23,43.18
ROM_A15  (via drill 0.3 pad 0.61)
  Top 0.203: v44.45,35.31 IC1.39 | v24.26,44.2 20.83,44.2 19.81,45.21 16.52,45.21 IC2.32
  Bottom 0.203: v44.45,35.31 44.07,35.31 34.8,44.7 24.77,44.7 v24.26,44.2
ROM_A16
  Top 0.203: IC1.38 42.42,34.04 40.13,36.32 40.13,41.15 34.95,46.33 18.77,46.33 18.41,45.97 16.56,45.97 IC2.33
ROM_A17  (via drill 0.3 pad 0.61)
  Top 0.203: v40.77,37.08 40.77,41.28 35.18,46.86 17.14,46.86 16.26,47.75 14.81,47.75 IC2.34 | v40.89,33.53 40.89,33.15 41.27,32.77 IC1.37
  Bottom 0.203: v40.77,37.08 40.77,33.66 v40.89,33.53
ROM_A18  (via drill 0.3 pad 0.61)
  Top 0.203: v41.53,36.45 41.53,41.4 35.56,47.37 17.4,47.37 15.88,48.9 13.59,48.9 13.08,48.39 13.08,47.85 IC2.36 | v42.04,31.5 IC1.36
  Bottom 0.203: v41.53,36.45 41.53,32 v42.04,31.5
ROM_A19  (via drill 0.3 pad 0.61)
  Top 0.203: v42.16,35.69 42.16,41.53 35.81,47.88 17.53,47.88 16.13,49.28 13.08,49.28 12.45,48.64 12.45,47.79 IC2.37 | v42.8,30.23 IC1.35
  Bottom 0.203: v42.16,35.69 42.16,32.39 42.55,32 42.55,30.48 v42.8,30.23
ROM_A20  (via drill 0.3 pad 0.61)
  Top 0.203: IC1.32 45.34,26.42 38.99,32.89 38.99,41.4 34.54,45.85 23.37,45.85 v22.99,45.47 | v11.3,44.07 11.3,46.48 11.56,46.74 11.56,47.7 IC2.38
  Bottom 0.203: v22.99,45.47 20.95,43.43 11.81,43.43 v11.3,44.07
ROM_A21  (via drill 0.3 pad 0.61)
  Top 0.203: IC1.31 45.97,25.15 38.23,32.89 38.23,41.28 34.16,45.34 23.75,45.34 23.11,44.7 21.34,44.7 v21.21,44.83 | v10.54,45.09 10.54,46.48 10.79,46.74 IC2.39
  Bottom 0.203: v21.21,44.83 21.08,44.7 10.92,44.7 v10.54,45.09
VCC  (via drill 0.3, 0.3 pad 0.61)
  Top 0.254: IC2.26 17.73,40.44 17.91,40.26 17.91,37.47 v17.4,36.96 | v20.19,36.83 20.19,35.24 C5.1
  Top 0.305: IC2.15 9.14,36.39 v9.14,38.48 | v10.79,38.48 11.3,38.99 12.7,38.99 14.15,40.44 IC2.26 | 9.78,52.07 11.05,50.8 v13.59,50.8 | IC2.35 13.97,47.76 | v13.97,45.59 11.43,43.05 9.14,43.05 v7.37,41.28
  Top 0.406: C1.1 2.73,50.93 4.95,50.93 5.97,51.94 IC4.8 7.37,51.92 7.37,51.82 | GBCONN.1 2,9.65 C4.1 2.56,11.16 1.02,12.7 1.02,45.59 1.91,46.48 3.94,46.48 5.59,48.13 5.59,49.53 7.37,51.31 7.37,51.82 | 7.37,51.82 7.11,52.07 9.78,52.07 10.54,52.83 10.54,57.4 11.05,57.91 37.34,57.91 38.1,57.15 38.1,51.54 IC1.44 49.91,41.66 50.29,41.28 50.29,15.49 49.78,14.99 IC1.23 47.98,11.47 C3.1 | v13.97,45.59 13.97,47.71 IC2.35
  Bottom 0.254: v17.4,36.96 20.07,36.96 v20.19,36.83
  Bottom 0.305: v10.79,38.48 v9.14,38.48 9.02,38.61 9.02,38.99 7.37,40.64 v7.37,41.28
  Bottom 0.406: v13.59,50.8 13.59,45.97 v13.97,45.59

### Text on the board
Bottom: DAVID PELLO 2008 | LADECADENCE.NET | Thanks to: Karawapo, Serranoc123, 3L_S4N70, The_Punisher & Gp32Spain Forums | Kraku & Chroost (GBCartFlasher) & Jeff Frohwein & Reiner Ziegler GameBoy Masters | #mundo_viejuno crew, #gbdev people, my girlfriend, friends and family 4 being there. | Licensed under a Creative-Commons CC-BY License, http://creativecommons.org
tNames: BATT | LADECADENCE.NET | DAVID PELLO | 2010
